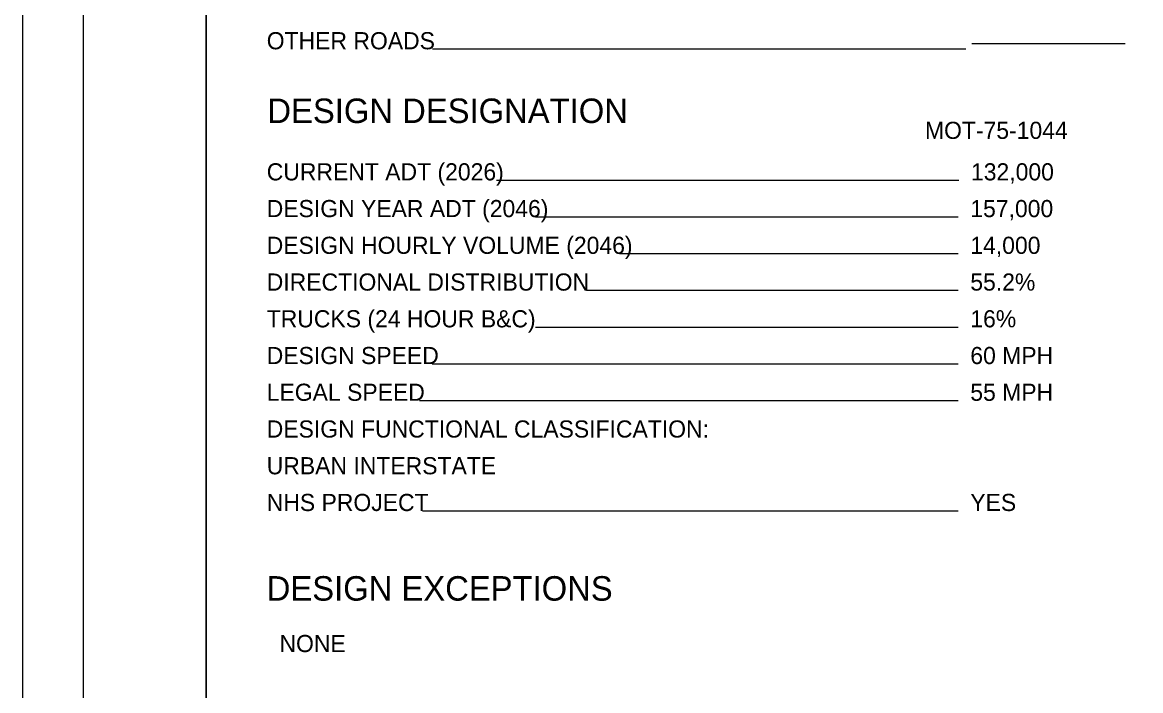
# Model space of a CAD drawing. Extents: x 0 to 34, y 0 to 22.
# Drawn here: x 0 to 9.13, y 5.64 to 11.1 of the extents above; entities that cross this region are included whole.
import ezdxf

# ---------------------------------------------------------------- set-up
doc = ezdxf.new("R2010")
doc.units = 0
for name, color, linetype in [('SH_Border', 7, 'Continuous'), ('SH_Cut_Line', 7, 'Continuous'), ('SH_Data', 7, 'Continuous'), ('SH_Text', 7, 'Continuous')]:
    doc.layers.add(name, color=color, linetype=linetype)

msp = doc.modelspace()

# ---------------------------------------------------------------- linework, layer by layer
at = {"layer": 'SH_Border'}
for points in [[(0.5, 21.5), (1.5, 21.5), (1.5, 0.5), (0.5, 0.5)], [(1.5, 21.5), (33.5, 21.5), (33.5, 0.5), (1.5, 0.5)]]:
    msp.add_lwpolyline(points, close=True, dxfattribs=at)
at = {"layer": 'SH_Cut_Line'}
msp.add_lwpolyline([(0, 0), (34, 0), (34, 22), (0, 22)], close=True, dxfattribs=at)
at = {"layer": 'SH_Data'}
for p, q in [((7.7, 10.8767), (3.3471, 10.8767)), ((9, 10.9223), (7.75, 10.9223)), ((7.6424, 9.8062), (3.871, 9.8062)), ((7.6368, 9.5062), (4.1885, 9.5062)), ((7.6368, 9.2062), (4.8723, 9.2062)), ((7.6368, 8.9062), (4.6037, 8.9062)), ((7.6368, 8.6062), (4.1885, 8.6062)), ((7.6368, 8.3062), (3.346, 8.3062)), ((7.6368, 8.0062), (3.2422, 8.0062)), ((7.6368, 7.1062), (3.2669, 7.1062))]:
    msp.add_line(p, q, dxfattribs=at)

# ---------------------------------------------------------------- texts
msp.add_text('DESIGN DESIGNATION', height=0.2, dxfattribs=at).set_placement((2, 10.2747))
at = {"layer": 'SH_Text'}
for s, height, p in [('OTHER ROADS', 0.14, (1.9944, 10.8767)), ('MOT-75-1044 ', 0.14, (7.3667, 10.1449)), ('CURRENT ADT (2026)', 0.14, (1.9944, 9.8062)), ('132,000', 0.14, (7.7424, 9.8062)), ('DESIGN YEAR ADT (2046)', 0.14, (1.9944, 9.5062)), ('157,000', 0.14, (7.7368, 9.5062)), ('DESIGN HOURLY VOLUME (2046)', 0.14, (1.9944, 9.2062)), ('14,000', 0.14, (7.7368, 9.2062)), ('DIRECTIONAL DISTRIBUTION', 0.14, (1.9944, 8.9062)), ('55.2%', 0.14, (7.7368, 8.9062)), ('TRUCKS (24 HOUR B&C)', 0.14, (1.9944, 8.6062)), ('16%', 0.14, (7.7368, 8.6062)), ('DESIGN SPEED', 0.14, (1.9944, 8.3062)), ('60 MPH', 0.14, (7.7368, 8.3062)), ('LEGAL SPEED', 0.14, (1.9944, 8.0062)), ('55 MPH', 0.14, (7.7368, 8.0062)), ('DESIGN FUNCTIONAL CLASSIFICATION:', 0.14, (1.9944, 7.7062)), ('URBAN INTERSTATE', 0.14, (1.9944, 7.4062)), ('NHS PROJECT', 0.14, (1.9944, 7.1062)), ('YES', 0.14, (7.7368, 7.1062)), ('DESIGN EXCEPTIONS', 0.2, (1.9944, 6.3744)), ('  NONE                                   ', 0.14, (1.9944, 5.9544))]:
    msp.add_text(s, height=height, dxfattribs=at).set_placement(p)

doc.saveas('drawing.dxf')
